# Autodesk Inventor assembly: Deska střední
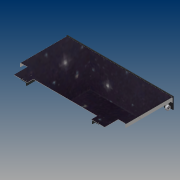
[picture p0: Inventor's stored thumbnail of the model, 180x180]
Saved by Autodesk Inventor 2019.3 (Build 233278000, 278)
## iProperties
Created: 2019-02
Part Number: Deska střední
Material: Všeobecné
Document SubType Name: Assembly
Designer: B-hon
Author: B-hon
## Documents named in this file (8)
- C:\Users\B-hon\OneDrive\Plocha\Bakalářka22\Deska střední\Deska střední.iam
- C:\Users\B-hon\OneDrive\Plocha\Bakalářka22\Deska střední\Výztuha1s.ipt
- C:\Users\B-hon\OneDrive\Plocha\Bakalářka22\Deska střední\Výztuha2s.ipt
- C:\Users\B-hon\OneDrive\Plocha\Bakalářka22\Rolna leva.iam
- C:\Users\B-hon\OneDrive\Plocha\Bakalářka22\Rolna prava.iam
- C:\Users\B-hon\OneDrive\Plocha\Bakalářka22\Deska střední\Plech desky1s.ipt
- C:\Users\B-hon\OneDrive\Plocha\Bakalářka22\Deska střední\Lišta1s.ipt
- C:\Users\B-hon\OneDrive\Documents\Inventor\Content Center Files\R2019\cs-CZ\DIN 7991(2)\DIN 7991 - M5x8.ipt
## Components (14 placed, 7 different names)
1. Plech desky1s:1 — Vložit:5, Vložit:6, Vložit:11, Vložit:12, Vložit:13, Vložit:14
2. Lišta1s:1 — Vložit:5, Vložit:6, Vložit:7, Vložit:8, Vložit:9, Vložit:10
3. Rolna leva:1 [sub-assembly] — Vložit:7, Vložit:10
4. Rolna prava:1 [sub-assembly] — Vložit:8, Vložit:9
5. Výztuha1s:1 — Vložit:13, Vložit:14
6. Výztuha2s:1 — Vložit:11, Vložit:12
7. DIN 7991 M5x8:5
8. DIN 7991 M5x8:6
9. DIN 7991 M5x8:7
10. DIN 7991 M5x8:8
11. DIN 7991 M5x8:1
12. DIN 7991 M5x8:2
13. DIN 7991 M5x8:3
14. DIN 7991 M5x8:4
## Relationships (10: Insert 10)
- Vložit:5 [Insert]: Plech desky1s:1 ↔ Lišta1s:1
- Vložit:6 [Insert]: Plech desky1s:1 ↔ Lišta1s:1
- Vložit:7 [Insert]: Lišta1s:1 ↔ Rolna leva:1
- Vložit:8 [Insert]: Lišta1s:1 ↔ Rolna prava:1
- Vložit:9 [Insert]: Lišta1s:1 ↔ Rolna prava:1
- Vložit:10 [Insert]: Lišta1s:1 ↔ Rolna leva:1
- Vložit:11 [Insert]: Plech desky1s:1 ↔ Výztuha2s:1
- Vložit:12 [Insert]: Plech desky1s:1 ↔ Výztuha2s:1
- Vložit:13 [Insert]: Plech desky1s:1 ↔ Výztuha1s:1
- Vložit:14 [Insert]: Plech desky1s:1 ↔ Výztuha1s:1
